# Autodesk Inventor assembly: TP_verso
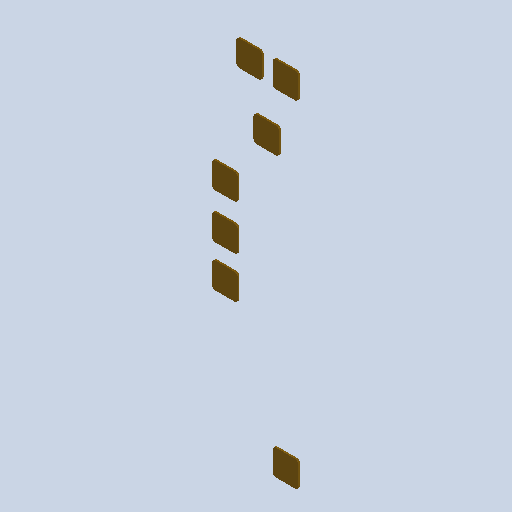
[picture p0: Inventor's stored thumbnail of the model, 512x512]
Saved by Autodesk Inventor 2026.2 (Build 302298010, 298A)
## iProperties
Created: 2026-10
Part Number: TP_verso
Document SubType Name: Assembly
Designer: mel
Author: mel
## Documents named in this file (8)
- D:\travail\année 2026-2027\1 sti2d IT\poubelle à verre\raspberry-pico-2-microcontroller-rp2350-1.snapshot.5\raspberry_pico_2\raspberry_pico_2\TP_verso.iam
- D:\travail\année 2026-2027\1 sti2d IT\poubelle à verre\raspberry-pico-2-microcontroller-rp2350-1.snapshot.5\raspberry_pico_2\raspberry_pico_2\TP2.ipt
- D:\travail\année 2026-2027\1 sti2d IT\poubelle à verre\raspberry-pico-2-microcontroller-rp2350-1.snapshot.5\raspberry_pico_2\raspberry_pico_2\TP3.ipt
- D:\travail\année 2026-2027\1 sti2d IT\poubelle à verre\raspberry-pico-2-microcontroller-rp2350-1.snapshot.5\raspberry_pico_2\raspberry_pico_2\TP1.ipt
- D:\travail\année 2026-2027\1 sti2d IT\poubelle à verre\raspberry-pico-2-microcontroller-rp2350-1.snapshot.5\raspberry_pico_2\raspberry_pico_2\TP4.ipt
- D:\travail\année 2026-2027\1 sti2d IT\poubelle à verre\raspberry-pico-2-microcontroller-rp2350-1.snapshot.5\raspberry_pico_2\raspberry_pico_2\TP5.ipt
- D:\travail\année 2026-2027\1 sti2d IT\poubelle à verre\raspberry-pico-2-microcontroller-rp2350-1.snapshot.5\raspberry_pico_2\raspberry_pico_2\TP6.ipt
- D:\travail\année 2026-2027\1 sti2d IT\poubelle à verre\raspberry-pico-2-microcontroller-rp2350-1.snapshot.5\raspberry_pico_2\raspberry_pico_2\TP_noname.ipt
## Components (7 placed, 7 different names)
1. 2783
2. 2784
3. 2785
4. 2786
5. 2787
6. 2788
7. 2789
